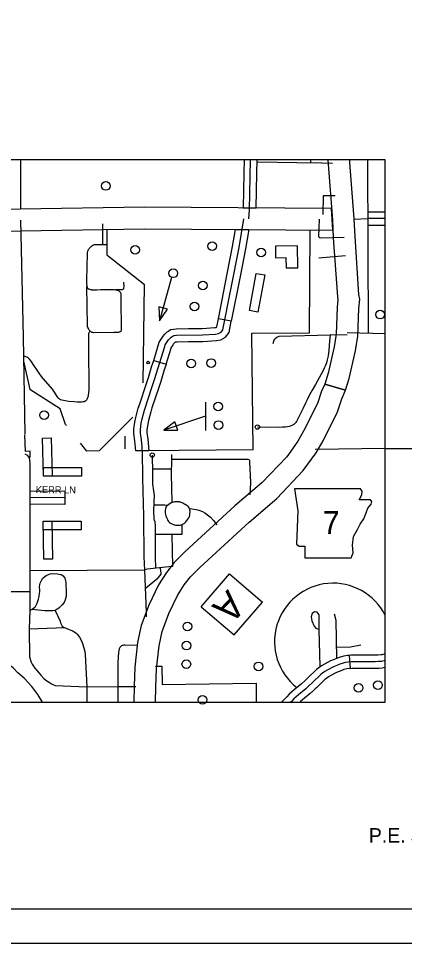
# Model space of a CAD drawing. Extents: x 19118 to 454486, y 1325406 to 1693506.
# Drawn here: x 25720 to 26165, y 1325406 to 1326473 of the extents above; entities that cross this region are included whole.
import ezdxf

# ---------------------------------------------------------------- set-up
doc = ezdxf.new("R2010")
doc.units = 0
for name, color, linetype in [('Default', 7, 'Continuous'), ('S_CURB', 7, 'Continuous'), ('S_EDGE_PAVEMENT', 7, 'Continuous'), ('S_SHOULDER', 7, 'Continuous')]:
    doc.layers.add(name, color=color, linetype=linetype)

msp = doc.modelspace()

# ---------------------------------------------------------------- linework, layer by layer
at = {"layer": 'Default'}
for p, q in [((25965, 1326123.4), (25950.3, 1326126.2)), ((25950.3, 1326126.2), (25950.3, 1326126.2)), ((25725.7, 1326077.5), (25732.9, 1326044.6)), ((25875.8, 1326078.4), (25890.1, 1326074.1)), ((25890.1, 1326074.1), (25890.1, 1326074.1)), ((25870.1, 1325974.2), (25855, 1325974.1)), ((25773.2, 1325927.3), (25773, 1325912.3)), ((25930.5, 1325794.3), (25963.1, 1325832.2)), ((25963.1, 1325832.2), (26001, 1325799.6)), ((25968.4, 1325761.7), (26001, 1325799.6)), ((25930.5, 1325794.3), (25968.4, 1325761.7)), ((26100.9, 1325738), (26102.2, 1325723.1)), ((26102.2, 1325723.1), (26102.2, 1325723.1))]:
    msp.add_line(p, q, dxfattribs=at)
for points in [[(25722, 1326309.7), (25722, 1326252.7)], [(25979.8, 1326309.7), (25979.5, 1326294.3)], [(25985.2, 1326241.4), (25986.3, 1326251.8), (25987.3, 1326309.7)], [(25994.5, 1326294), (25994.8, 1326309.7)], [(26056.6, 1326309.7), (26056.6, 1326306.5)], [(26076.6, 1326309.7), (26077, 1326304.8), (26081.8, 1326240.1), (26082.8, 1326219.7), (26087.6, 1326151.6), (26088.1, 1326148), (26087.4, 1326139.8), (26086.2, 1326108.7), (26083.8, 1326094.1), (26076.7, 1326063.8), (26072.9, 1326051.1), (26096.9, 1326044)], [(26096.9, 1326044), (26100.9, 1326057.4), (26108.3, 1326089.2), (26111.2, 1326106.1), (26112.4, 1326138.3), (26113.2, 1326148.8), (26112.4, 1326154.3), (26107.8, 1326221.2), (26106.7, 1326241.7), (26101.9, 1326306.6), (26101.7, 1326309.7)], [(26122.4, 1326309.7), (26123, 1326109.9)], [(26069.1, 1326306.2), (26063.8, 1326305.6), (25994.8, 1326306.9)], [(26069.1, 1326306.2), (26081.9, 1326305.9)], [(25979.5, 1326294.3), (25978.9, 1326254.2), (25993.9, 1326254.1)], [(25993.9, 1326254.1), (25994.5, 1326294)], [(26085.1, 1326268.2), (26071, 1326268.2), (26070.6, 1326246.5)], [(26082.4, 1326228.5), (26080.8, 1326253.5), (25865, 1326254.9), (25721.7, 1326252.7), (25591.1, 1326249.8), (25459.1, 1326249.1), (25411.7, 1326247.9), (25344.7, 1326247.8), (25279.9, 1326248.7), (25156.7, 1326248.6), (25177.1, 1326223.7)], [(26132.6, 1326249.3), (26122.6, 1326249.3), (26122.6, 1326234.3)], [(26142.7, 1326249.3), (26132.6, 1326249.3)], [(25721.9, 1326240.2), (25725.2, 1326105.5), (25727.1, 1325993.4)], [(25816.5, 1326235.7), (25816.5, 1326211.6)], [(25902, 1326107.3), (25931.9, 1326107.7), (25947, 1326108.6), (25950.3, 1326109.3), (25953.4, 1326111), (25955.5, 1326113.7), (25974.1, 1326208.5), (25979.7, 1326241.4)], [(26066.3, 1326241.3), (26065.8, 1326221.4), (26066.7, 1326220.2), (26068.1, 1326219.5), (26095.3, 1326220.5)], [(26106.7, 1326241.3), (26122.6, 1326241.8)], [(26142.7, 1326241.8), (26122.6, 1326241.8)], [(25177.1, 1326223.7), (25279.8, 1326223.7), (25344.6, 1326222.8), (25412, 1326222.9), (25459.4, 1326224.1), (25591.4, 1326224.8), (25722.2, 1326227.7), (25865.1, 1326229.9), (26082.4, 1326228.5)], [(25821.5, 1326229.3), (25821.5, 1326200.1)], [(25960.5, 1326178.1), (25966.7, 1326209.8), (25970, 1326229.2), (25985.2, 1326229.1)], [(25985.2, 1326229.1), (25981.4, 1326207.1), (25975.2, 1326175.2)], [(25990.5, 1325975.1), (25988.9, 1326109.7), (26055.5, 1326110.1), (26056.1, 1326228.9)], [(26122.6, 1326234.3), (26132.6, 1326234.3)], [(26132.6, 1326234.3), (26142.7, 1326234.3)], [(25821.3, 1326211.6), (25808.2, 1326211.6), (25807.1, 1326211.5), (25806, 1326211.1), (25805.3, 1326210.7), (25804.3, 1326210.1), (25803.6, 1326209.5), (25802.7, 1326208.8), (25802.1, 1326208.3), (25801.5, 1326207.7), (25801.1, 1326207.3), (25800.7, 1326206.6), (25800.2, 1326206), (25799.9, 1326205.4), (25799.6, 1326204.8), (25799.3, 1326204.1), (25799.2, 1326203.5), (25799, 1326202.7), (25798.9, 1326201.8), (25798.3, 1326170.8), (25798.3, 1326167), (25798.5, 1326164.5), (25798.6, 1326163.6), (25798.8, 1326162.9), (25799.1, 1326162.1), (25799.5, 1326161.5), (25800.1, 1326161), (25800.7, 1326160.7), (25801.7, 1326160.3), (25802.7, 1326160.1), (25803.4, 1326160), (25804.1, 1326159.9), (25805.7, 1326159.9), (25810.1, 1326159.9), (25814.3, 1326160), (25830.2, 1326160), (25831.7, 1326159.9), (25832.8, 1326159.8), (25834, 1326159.3), (25834.9, 1326158.8), (25835.9, 1326158.1), (25836.6, 1326157.4), (25837, 1326157), (25837.3, 1326156.5), (25837.5, 1326156.1), (25837.6, 1326155.6), (25837.7, 1326155), (25837.7, 1326153.5), (25837.7, 1326149.1), (25838.1, 1326113.5), (25838.1, 1326112.7), (25837.9, 1326112.1), (25837.6, 1326111.7), (25837.1, 1326111.3), (25836.6, 1326111.1), (25835.9, 1326110.8), (25835.2, 1326110.6), (25834.5, 1326110.4), (25832.5, 1326110.4), (25829.8, 1326110.4), (25806.2, 1326110.3), (25805.4, 1326110.4), (25804.8, 1326110.5), (25804.4, 1326110.6), (25803.5, 1326111.2), (25802.7, 1326111.8), (25801.9, 1326112.5), (25801.2, 1326113.3), (25800.7, 1326114.1), (25800.3, 1326115), (25799.8, 1326116.2), (25799.5, 1326117.5), (25799.4, 1326118.9), (25798.6, 1326163.6)], [(25821.5, 1326200.1), (25865.2, 1326165.7)], [(26066, 1326196.8), (26096.7, 1326199.3)], [(25896.2, 1326173.9), (25882.5, 1326124)], [(25950.3, 1326126.2), (25960.5, 1326178.1)], [(25975.2, 1326175.2), (25965, 1326123.4)], [(25841, 1326168.5), (25841.1, 1326163.4), (25841, 1326161.9), (25840.9, 1326161.3), (25840.8, 1326160.9), (25840.6, 1326160.6), (25840.3, 1326160.2), (25839.9, 1326160), (25839.4, 1326159.9), (25838.8, 1326159.9), (25831.7, 1326159.9)], [(25863.5, 1326052.4), (25865.2, 1326165.7)], [(25915.8, 1326115), (25931.6, 1326115.2), (25946, 1326116.1), (25947.6, 1326116.4), (25948.5, 1326116.9), (25948.5, 1326116.9), (25950.3, 1326126.2)], [(25915.9, 1326100), (25932.2, 1326100.2), (25948, 1326101.2), (25952.9, 1326102.2), (25958.4, 1326105.2), (25962.5, 1326110.5), (25965, 1326123.4)], [(25802.4, 1326112.1), (25801.7, 1326111.3), (25801.2, 1326110.7), (25800.9, 1326110.2), (25800.7, 1326109.7), (25800.6, 1326109.3), (25800.5, 1326108.5), (25800.4, 1326107.8), (25800.4, 1326107), (25800.4, 1326106.1), (25800.6, 1326072), (25800.8, 1326066.5), (25801, 1326047.6), (25800.9, 1326044.2), (25800.6, 1326041.3), (25800, 1326037.8), (25799.6, 1326035.9), (25799.1, 1326034.5), (25798.6, 1326033.3), (25798, 1326032.3), (25797.4, 1326031.7), (25796.3, 1326031), (25795.3, 1326030.7), (25794.2, 1326030.4), (25792.9, 1326030.2), (25791.8, 1326030.1), (25790.8, 1326030.2), (25787.3, 1326030.3), (25784.1, 1326030.6), (25777.9, 1326031.1), (25773.4, 1326031.7), (25769.9, 1326032.3), (25768.3, 1326033), (25766.9, 1326033.8), (25765.5, 1326035.3), (25764.4, 1326036.7), (25761.4, 1326041.7), (25758.8, 1326045.1), (25748.6, 1326057.1), (25746.2, 1326059.9), (25743.6, 1326063.5), (25741.3, 1326066.9), (25737.7, 1326072.1), (25734.3, 1326077.6), (25732.5, 1326079.9), (25731.4, 1326080.9), (25730.3, 1326081.7), (25729.3, 1326082.1), (25728.3, 1326082.5), (25727.3, 1326082.8), (25726.4, 1326083), (25725.6, 1326083)], [(25862.5, 1325974.1), (25862.2, 1325978.5), (25861.6, 1325986.6), (25860.4, 1325994.6), (25860.4, 1325998.8), (25861.4, 1326005.9), (25862.4, 1326010.8), (25865, 1326021), (25874, 1326048.3), (25876.7, 1326056.4), (25880.7, 1326069.6), (25882.5, 1326074.8), (25888.5, 1326094.5), (25889, 1326096.1), (25890.6, 1326098.5), (25892.8, 1326101.9), (25894.1, 1326103.7), (25895.9, 1326105.3), (25896.9, 1326106), (25898, 1326106.8), (25899.4, 1326106.9), (25902, 1326107.3)], [(25875.8, 1326078.4), (25881.3, 1326096.7), (25882.1, 1326099.3), (25884.3, 1326102.7), (25886.7, 1326106.2), (25888.5, 1326108.7), (25891.3, 1326111.3), (25892.6, 1326112.1), (25895.2, 1326114), (25898.4, 1326114.4), (25901.4, 1326114.8), (25915.8, 1326115)], [(26079.2, 1326107.7), (26078.5, 1326100.4), (26077.6, 1326090.2), (26076.7, 1326083.5), (26075.8, 1326078.8), (26074.9, 1326075.4), (26074.2, 1326073.5), (26073.4, 1326071.5), (26072.4, 1326069.3), (26071.1, 1326066.5), (26068.8, 1326062.5), (26062.1, 1326050.7), (26058.4, 1326044.2), (26055.4, 1326038.6), (26052.6, 1326032.9), (26050.7, 1326029.2), (26048.2, 1326023.4), (26041.1, 1326009.4), (26040.2, 1326007.7), (26039.5, 1326006.7), (26038.7, 1326005.8), (26037.3, 1326004.6), (26035.8, 1326003.5), (26034, 1326002.7), (26032, 1326002.1), (26030, 1326001.6), (26027.5, 1326001.4), (26024.2, 1326001.2), (26019.8, 1326001.1), (25995.2, 1326001.4)], [(26013.6, 1326097.9), (26014.2, 1326100.7), (26015, 1326102.7), (26015.3, 1326103), (26015.7, 1326103.4), (26017.7, 1326105.2), (26020.4, 1326106.4), (26079.2, 1326107.7)], [(26098.7, 1326107.4), (26079.2, 1326107.7)], [(26098.8, 1326110.6), (26142.7, 1326109.3)], [(25890.1, 1326074.1), (25895.7, 1326092.3), (25895.8, 1326092.9), (25896.8, 1326094.4), (25899, 1326097.7), (25899.7, 1326098.7), (25900.5, 1326099.4), (25900.8, 1326099.6), (25902.6, 1326099.9), (25915.9, 1326100)], [(25859.5, 1326028.4), (25866.9, 1326050.7), (25869.6, 1326058.7), (25873.6, 1326071.9), (25875.4, 1326077.1), (25875.8, 1326078.4)], [(25890.1, 1326074.1), (25889.7, 1326072.5), (25887.9, 1326067.3), (25883.9, 1326054.1), (25881.1, 1326045.9), (25873.7, 1326023.7)], [(25767.8, 1326022.3), (25732.9, 1326044.6)], [(26096.9, 1326044), (26072.9, 1326051.1), (26069.3, 1326043), (26064.5, 1326028.8), (26048.9, 1325997.4), (26042, 1325985.3), (26029, 1325967.3), (26000.3, 1325937.1), (25969.3, 1325910.5), (25911.6, 1325857.5), (25899.3, 1325845.4), (25890.4, 1325833.8), (25881.2, 1325819.6), (25869.9, 1325796), (25861.4, 1325772.6), (25857.1, 1325753), (25854.1, 1325724.5), (25853, 1325702.6), (25852.6, 1325684.1)], [(25877.6, 1325684.1), (25878, 1325701.7), (25879, 1325722.5), (25881.8, 1325749), (25885.5, 1325765.6), (25893, 1325786.3), (25903.1, 1325807.3), (25910.9, 1325819.4), (25918.1, 1325828.8), (25928.9, 1325839.4), (25985.9, 1325891.8), (26017.5, 1325918.9), (26048.2, 1325951.3), (26063, 1325971.7), (26071, 1325985.6), (26087.6, 1326019.2), (26092.7, 1326034), (26096.9, 1326044)], [(25774, 1326004.6), (25767.8, 1326022.3)], [(25855, 1325974.1), (25854.1, 1325985.7), (25852.9, 1325994.1), (25852.9, 1325999.3), (25854, 1326007.2), (25855.1, 1326012.4), (25857.7, 1326023.1), (25859.5, 1326028.4)], [(25873.7, 1326023.7), (25872.2, 1326018.9), (25869.7, 1326009.1), (25868.8, 1326004.7), (25867.9, 1325998.3), (25867.9, 1325995.2), (25869, 1325987.4), (25870.1, 1325974.2)], [(25935.5, 1326030.3), (25935.5, 1325997.6)], [(25851.5, 1326012.7), (25812.8, 1325973.9)], [(25935.5, 1326014), (25887.3, 1325997.7)], [(25775.1, 1326003.3), (25774, 1326004.6)], [(25733.1, 1325966.3), (25733.3, 1325973.5), (25727.9, 1325973.4), (25727.1, 1325992.6)], [(25842.5, 1325990.8), (25842.5, 1325976.2)], [(25747.3, 1325684.1), (25741.9, 1325693.2), (25735.2, 1325702.4), (25726.3, 1325711.8), (25719, 1325718.1), (25713.8, 1325723.7), (25705, 1325729.9), (25694.8, 1325738.4), (25681.9, 1325747.3), (25659.4, 1325764.9), (25513.9, 1325869.3), (25397, 1325954.1), (25357.2, 1325982.5), (25342.2, 1325962.5)], [(25798.5, 1325973.8), (25791.2, 1325983)], [(25726.9, 1325970.4), (25729.8, 1325968.9), (25731.9, 1325966), (25733, 1325960.1), (25733, 1325920.2), (25732.8, 1325904.6)], [(25812.8, 1325973.9), (25798.5, 1325973.8)], [(25990.5, 1325975.1), (25862.5, 1325974.1)], [(25862.5, 1325974.1), (25862.9, 1325942.6), (25863.9, 1325898.8), (25864.4, 1325852), (25864.9, 1325836.3), (25866.9, 1325787.7), (25866.8, 1325782.8)], [(25874, 1325969.2), (25874.4, 1325948.5), (25874.4, 1325935.6), (25875.5, 1325927.9), (25876.1, 1325922.5), (25875.9, 1325915.6), (25875.5, 1325903.1), (25875.7, 1325897.6), (25875.7, 1325895.5), (25876.3, 1325893.9), (25876.9, 1325892.9), (25877.1, 1325891.6), (25877.3, 1325887.9), (25877.3, 1325874.2), (25877.3, 1325852.1), (25877.7, 1325838.5)], [(25896.1, 1325970), (25896.1, 1325964.4), (25895.8, 1325945.8), (25896.1, 1325932.4), (25896.4, 1325914.2)], [(26142.7, 1325976.6), (26061.9, 1325975.6)], [(25896.1, 1325964.4), (25943.1, 1325964.4), (25955.6, 1325964.4), (25984.3, 1325964.3), (25985.2, 1325964.1), (25985.9, 1325963.6), (25986.1, 1325963), (25986.2, 1325962.2), (25986.3, 1325961.2), (25987.2, 1325937.4), (25986.6, 1325923.5)], [(25874.4, 1325953.1), (25895.9, 1325953.1)], [(25773.2, 1325927.3), (25733, 1325927.7)], [(25773.1, 1325919.8), (25733, 1325920.2)], [(25908.5, 1325914), (25907.5, 1325914.4), (25906.4, 1325914.8), (25905.9, 1325915), (25905.3, 1325915.1), (25904.6, 1325915.2), (25904.1, 1325915.3), (25902.6, 1325915.4), (25901.2, 1325915.3), (25899.8, 1325915.2), (25898.6, 1325915), (25896.7, 1325914.3), (25894.7, 1325913.4), (25893, 1325912.3), (25891.5, 1325911.1), (25890.6, 1325910.1), (25889.8, 1325908.9), (25889.3, 1325907.3), (25889, 1325905.7), (25888.9, 1325904), (25889, 1325902.3), (25889.3, 1325900.6), (25889.7, 1325899.1), (25890.5, 1325897.1), (25891.5, 1325894.8), (25892.1, 1325893.6), (25892.8, 1325892.6), (25893.4, 1325891.8), (25894, 1325891.3), (25895.1, 1325890.6), (25896.4, 1325889.8), (25898.4, 1325889), (25899.5, 1325888.7), (25900.7, 1325888.4), (25902, 1325888.3), (25903.2, 1325888.2), (25905.3, 1325888.4), (25906.4, 1325888.5), (25907.5, 1325888.8), (25908.6, 1325889.2), (25909.8, 1325889.7), (25910.7, 1325890.3), (25911.5, 1325891.1), (25912.7, 1325892.2), (25913.9, 1325893.6), (25915, 1325895.2), (25916.1, 1325896.9), (25916.8, 1325898.5), (25917.2, 1325900.2), (25917.5, 1325901.9), (25917.6, 1325903.7), (25917.6, 1325904.6), (25917.5, 1325905.6), (25917.3, 1325906.5), (25917, 1325907.5), (25916.5, 1325908.3), (25915.9, 1325909.3), (25915, 1325910.1), (25913.9, 1325910.9), (25912.1, 1325912.1), (25910.3, 1325913.1), (25909.4, 1325913.6), (25908.5, 1325914)], [(25732.8, 1325904.6), (25732.9, 1325835.7)], [(25773, 1325912.3), (25732.9, 1325912.7)], [(25875.7, 1325911.8), (25888.6, 1325911.8), (25892, 1325911.5)], [(25916.8, 1325907.7), (25924.5, 1325906.5), (25927.8, 1325905.7), (25931.8, 1325904.2), (25934.8, 1325902.5), (25937.8, 1325900.3), (25941.2, 1325897.5), (25944.6, 1325893.6), (25948.3, 1325888.9), (25948.4, 1325888.7)], [(25908.2, 1325889), (25908.3, 1325877.7), (25877.3, 1325877.6)], [(25896.7, 1325877.6), (25897.3, 1325840.6)], [(25897.6, 1325840.6), (25896.7, 1325840.6), (25875.1, 1325838.2), (25872.1, 1325837.9), (25868.7, 1325837.4), (25866.8, 1325837.2), (25864.9, 1325836.9)], [(25732.9, 1325835.7), (25733, 1325823.5), (25732.9, 1325811.5), (25732.8, 1325790.5), (25732.1, 1325768.3), (25732.5, 1325736.6), (25734.2, 1325730.3), (25735.7, 1325728.1), (25738.7, 1325723.6), (25741.4, 1325720.2), (25743.5, 1325717.7), (25745.5, 1325715.5), (25749.1, 1325711.7), (25752.6, 1325708.7), (25756.1, 1325706.4), (25758.5, 1325704.9), (25761.9, 1325703.5), (25798.4, 1325702), (25834.2, 1325702.1), (25855, 1325702.1)], [(25732.8, 1325790.5), (25735.1, 1325791.1), (25737.6, 1325792.9), (25739.2, 1325794.7), (25740.4, 1325796.8), (25741.3, 1325798.4), (25742.9, 1325803), (25743.5, 1325806.1), (25744, 1325809.8), (25744.2, 1325811.4), (25744.2, 1325813.8), (25744.1, 1325817), (25744.2, 1325819.8), (25744.6, 1325821.3), (25746.2, 1325824.7), (25747.6, 1325826.9), (25750.5, 1325829.5), (25752.6, 1325830.8), (25756.2, 1325832.1), (25759.5, 1325832.6), (25764.8, 1325832.4), (25768.9, 1325831.6), (25771.3, 1325829.9), (25773, 1325827.1), (25774.2, 1325822.7), (25774.5, 1325818.5), (25774.7, 1325814.6), (25774.9, 1325812.9), (25774.8, 1325809.7), (25774.6, 1325806.3), (25773.7, 1325802.1), (25772.3, 1325799.1), (25770.3, 1325796.3), (25767.9, 1325794.1), (25766.2, 1325792.7), (25764.2, 1325791.4), (25762, 1325790.1), (25759.4, 1325789.7), (25754, 1325789.6), (25750, 1325789.7), (25735.1, 1325791.1)], [(25864.9, 1325836.3), (25733, 1325835.7)], [(25883.1, 1325839.1), (25883.6, 1325835), (25883.8, 1325834.1), (25883.8, 1325832.8), (25883.8, 1325831.7), (25879.4, 1325826.2), (25865.8, 1325814.9)], [(25732.9, 1325811.5), (25702.2, 1325811.3), (25698.9, 1325810.2), (25697, 1325808.1), (25696, 1325803.1), (25696.1, 1325796.8)], [(25762, 1325790.1), (25767.7, 1325777.8), (25768.2, 1325775.8), (25768.5, 1325774.8), (25769.2, 1325773.4), (25770.2, 1325771.9), (25771.6, 1325770.8), (25773.5, 1325769.8), (25775.4, 1325769), (25778.2, 1325767.9), (25780.2, 1325767.1), (25782.5, 1325766.3), (25786.3, 1325763.8), (25787.5, 1325762.6), (25790.2, 1325759.2), (25792, 1325755.6), (25793.7, 1325751.8), (25795, 1325746.8), (25796.2, 1325742.5), (25796.6, 1325739.1), (25798.4, 1325702)], [(26067.8, 1325725.2), (26066.3, 1325768.1), (26066.4, 1325785.1), (26064.3, 1325788.1), (26061, 1325788.3), (26058.4, 1325786.5), (26057.2, 1325782.7), (26058.1, 1325778.1), (26060.7, 1325772), (26062.5, 1325769.6), (26066.3, 1325768.1)], [(26083.9, 1325786.1), (26085.8, 1325778.7), (26086.4, 1325734.6)], [(25773.5, 1325769.8), (25732.1, 1325768.3)], [(25857.4, 1325749.4), (25842.4, 1325749.8), (25841.3, 1325749.8), (25840.2, 1325749.7), (25839.4, 1325749.6), (25838.7, 1325749.3), (25837.7, 1325748.6), (25836.8, 1325747.3), (25836, 1325745.8), (25835.3, 1325743.9), (25834.9, 1325741.9), (25834.6, 1325736), (25834.3, 1325729)], [(26086.2, 1325747.7), (26102.7, 1325747.9), (26114.6, 1325750.3)], [(26100.9, 1325738), (26099.3, 1325737.9), (26095, 1325737.2), (26090.8, 1325736.1), (26087.7, 1325735.1), (26083.8, 1325733.6), (26079.7, 1325731.7), (26072.7, 1325728), (26069.2, 1325726), (26065.9, 1325723.8), (26063.3, 1325721.8), (26053.2, 1325712), (26051.5, 1325710.4)], [(26142.7, 1325739.8), (26142.6, 1325739.8), (26141.3, 1325739.4), (26139.9, 1325739.2), (26138.7, 1325738.9), (26137.4, 1325738.8), (26134.2, 1325738.5), (26131.1, 1325738.4), (26106.8, 1325738.4), (26103.4, 1325738.3), (26100.9, 1325738)], [(25834.3, 1325729), (25834.2, 1325702.1)], [(25877.8, 1325725.7), (25885.1, 1325725.8), (25885.6, 1325704.6), (25994, 1325706.1), (25993.9, 1325684.1)], [(26142.7, 1325732.1), (26141.3, 1325731.8), (26139.8, 1325731.5), (26138.2, 1325731.3), (26134.8, 1325731), (26131.2, 1325730.9), (26107, 1325730.9), (26103.9, 1325730.8), (26100.3, 1325730.5), (26096.6, 1325729.8), (26093, 1325728.9), (26090.2, 1325728), (26086.7, 1325726.6), (26083, 1325725), (26076.3, 1325721.4), (26073.2, 1325719.7), (26070.3, 1325717.8), (26068.3, 1325716.1), (26058.4, 1325706.6), (26054.7, 1325703), (26051.1, 1325699.7), (26042.6, 1325692.8), (26039.8, 1325690.4), (26037.4, 1325688.1), (26034.5, 1325685)], [(26102.2, 1325723.1), (26101.3, 1325723), (26098.2, 1325722.5), (26095.1, 1325721.7), (26092.7, 1325720.9), (26089.5, 1325719.7), (26086.3, 1325718.3), (26079.9, 1325714.9), (26077.1, 1325713.3), (26074.8, 1325711.7), (26073.2, 1325710.5), (26063.6, 1325701.2), (26061.8, 1325699.5)], [(26102.2, 1325723.1), (26104.4, 1325723.3), (26107.1, 1325723.4), (26131.4, 1325723.4), (26135.3, 1325723.5), (26139, 1325723.9), (26140.8, 1325724.1), (26142.7, 1325724.4)], [(25798.4, 1325702), (25798.4, 1325684.1)], [(25834.2, 1325702.1), (25834.3, 1325684.1)], [(26051.5, 1325710.4), (26049.5, 1325708.5), (26046.2, 1325705.4), (26037.8, 1325698.5), (26034.8, 1325696), (26032, 1325693.4), (26029.1, 1325690.2), (26023, 1325684.1)], [(26061.8, 1325699.5), (26059.8, 1325697.6), (26056, 1325694.1), (26047.3, 1325687), (26044.8, 1325684.9), (26044, 1325684.1)], [(26034.5, 1325685), (26033.6, 1325684.1)]]:
    msp.add_lwpolyline(points, dxfattribs=at)
for points in [[(26041.4, 1326210.5), (26016, 1326210.2), (26016.2, 1326196.8), (26028.2, 1326196.9), (26028.3, 1326184.9), (26041.7, 1326185.1)], [(25994, 1326178.7), (26003.8, 1326176.9), (25995.8, 1326133.9), (25986, 1326135.7)], [(25891.5, 1326137.4), (25881.6, 1326140.1), (25882.5, 1326124)], [(25903.4, 1325997.8), (25900.2, 1326007.4), (25887.3, 1325997.7)], [(25747.6, 1325988.7), (25757.6, 1325988.9), (25758.5, 1325945.2), (25748.5, 1325945)], [(25748.5, 1325945), (25748.5, 1325955), (25792.3, 1325955), (25792.3, 1325945)], [(26038.1, 1325930.3), (26041.9, 1325904.9), (26040.2, 1325866.5), (26043.6, 1325864.3), (26049.9, 1325864.3), (26049.9, 1325850.8), (26103.2, 1325850.8), (26105.8, 1325856.3), (26104.9, 1325865.2), (26106.2, 1325875.3), (26110.8, 1325883.4), (26113.8, 1325889.3), (26118, 1325895.6), (26120.6, 1325902.4), (26122.7, 1325907.9), (26126.5, 1325912.6), (26127.3, 1325915.5), (26125.6, 1325917.6), (26112.5, 1325917.6), (26115.5, 1325923.5), (26115.9, 1325927.4), (26114.2, 1325930.3)], [(25748.2, 1325892.8), (25758.2, 1325893), (25759.1, 1325849.2), (25749.1, 1325849)], [(25748.2, 1325882.8), (25748.2, 1325892.8), (25792, 1325892.8), (25792, 1325882.8)]]:
    msp.add_lwpolyline(points, close=True, dxfattribs=at)
for centre, radius in [((25820.5, 1326279.5), 5), ((25943, 1326210), 5), ((25854.2, 1326205.9), 5), ((25999.5, 1326202.7), 5), ((25898.3, 1326178.8), 5), ((25932.4, 1326164.7), 5), ((25922.8, 1326140.5), 5), ((26136.8, 1326131.1), 5), ((25869.3, 1326075.8), 1.5), ((25919, 1326074.8), 5), ((25942, 1326075.3), 5), ((25949.9, 1326025.2), 5), ((25749.2, 1326015.2), 5), ((25950.5, 1326003.8), 5), ((25995.2, 1326001.4), 2.5), ((25874, 1325969.2), 2.5), ((25914.5, 1325771.4), 5), ((25913.5, 1325749.4), 5), ((25913.3, 1325728), 5), ((25996.5, 1325725.5), 5), ((26112, 1325700.7), 5), ((26134.3, 1325703.9), 5), ((25932, 1325686.8), 5)]:
    msp.add_circle(centre, radius, dxfattribs=at)
msp.add_arc((26082.4, 1325754), 67.4, 26.5235, 231.8329, dxfattribs=at)
at = {"layer": 'S_CURB'}
msp.add_line((26142.7, 1325976.6), (26268, 1325976.6), dxfattribs=at)
msp.add_lwpolyline([(26142.7, 1326309.7), (24887.1, 1326309.7), (24887.1, 1325684.1), (26142.7, 1325684.1)], close=True, dxfattribs=at)
at = {"layer": 'S_EDGE_PAVEMENT'}
msp.add_lwpolyline([(23759.7, 1327539.3), (27093.1, 1327539.3), (27093.1, 1325405.9), (23759.7, 1325405.9)], close=True, dxfattribs=at)
at = {"layer": 'S_SHOULDER'}
msp.add_line((27045.6, 1325445.7), (23883.8, 1325445.7), dxfattribs=at)

# ---------------------------------------------------------------- texts
at = {"layer": 'Default'}
for s, height, rotation, p in [('KERR LN', 8, 359.3596, (25739.6, 1325925.4)), ('A', 31.7, 225.669, (25961.3, 1325815))]:
    msp.add_text(s, height=height, rotation=rotation, dxfattribs=at).set_placement(p)
msp.add_text('7', height=26.4, dxfattribs=at).set_placement((26070.5, 1325878.2))
at = {"layer": 'S_CURB'}
msp.add_text('P.E. JOB 090437', height=16.848, dxfattribs=at).set_placement((26123.7, 1325522.1))

doc.saveas('drawing.dxf')
